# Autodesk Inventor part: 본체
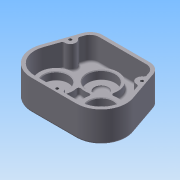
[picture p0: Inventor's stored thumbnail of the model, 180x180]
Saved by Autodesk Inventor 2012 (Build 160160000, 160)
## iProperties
Created: 2014-12
Part Number: 본체
Material: 알루미늄-6061
Document SubType Name: Modeling
Designer: Owner
Density: 2.71 g/cm^3
Mass: 613.436 g
Surface Area: 665.18 cm^2
Volume: 226.36 cm^3
Author: Owner
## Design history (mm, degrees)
sketch "스케치1"
  geometry: L1 (0, 0)-(-42.388, -42.388); L2 (0, 0)-(24.229, -24.229); L3 (-47, 36)-(47, 36); L4 (-47, 36)-(-66.565, -20.803); L5 (47, 36)-(66.565, -20.803); L6 (-32.527, -68.527)-(32.527, -68.527); A1 r 46 centre (0, 0) between (32.527, -32.527) and (-32.527, -32.527); A2 r 36 centre (-32.527, -32.527) between (-66.565, -20.803) and (-32.527, -68.527); A3 r 36 centre (32.527, -32.527) between (32.527, -68.527) and (66.565, -20.803); 3 further points
  constraints: 12 end point, 6 point on circle, 3 centre point, 3 tangent, 2 coincident, 2 midpoint, 2 point on line, 2 vertical alignment, 1 horizontal, 1 parallel
  dimensions: "d0" = 92 diameter of A1; "d1" = 90 deg angle of L2 L1; "d2" = 94 distance of L3.start L3.end; "d3" = 36 distance from line of L1.start L3; "d6" = 36 radius of A2; "d7" = 36 radius of A3
extrude "돌출1" new body sketch "스케치1" distance "d8" = 44; taper "d9" = 0 deg
sketch "스케치2"
  geometry: C1 r 20 at (-32.527, -32.527); C2 r 20 at (32.527, -32.527); A1 r 36 centre (-32.527, -32.527) between (-66.565, -20.803) and (-32.527, -68.527) reference; A2 r 36 centre (32.527, -32.527) between (32.527, -68.527) and (66.565, -20.803) reference; 1 further point
  constraints: 2 centre point, 2 coincident
  dimensions: "d10" = 40 diameter of C1; "d11" = 40 diameter of C2
extrude "돌출2" join sketch "스케치2" distance "d12" = 7; taper "d13" = 0 deg
chamfer "모따기1" distance "d14" = 7; stored, may be unused: second distance "d15" = 2, angle "d16" = 10 deg
sketch "스케치3"
  geometry: L1 (0, -44)-(94, -44) reference; L2 (94, 0)-(94, -44) reference; L3 (0, 0)-(94, 0) reference; L4 (0, 0)-(0, -44) reference; L5 (0, -44)-(0, 0) reference; L6 (0, 0)-(94, 0) reference; L7 (94, 0)-(94, -44) reference; L8 (94, -44)-(0, -44) reference; L9 (60.761, 7)-(59.527, 0) reference; L10 (79.527, 0)-(14.473, 0) reference; 1 further point
  node "절단 모서리 투영1"
chamfer "모따기2" distance "d17" = 7; stored, may be unused: second distance "d18" = 2, angle "d19" = 10 deg
fillet "모깎기1" dims "d20" = 18
hole "구멍1" diameter "d23" = 15.5; stored, may be unused: countersink angle "d27" = 90 deg, drill point angle "d29" = 118 deg; dims "d21" = 10, "d22" = 10, "d24" = 6, "d25" = 4, "d26" = 2, "d28" = 8
hole "구멍2" diameter "d32" = 15.5; stored, may be unused: countersink angle "d36" = 90 deg, drill point angle "d38" = 118 deg; dims "d30" = 10, "d31" = 10, "d33" = 6, "d34" = 4, "d35" = 2, "d37" = 8
hole "구멍3" diameter "d41" = 30; stored, may be unused: countersink angle "d45" = 90 deg, drill point angle "d47" = 0 deg; dims "d39" = 10, "d40" = 10, "d42" = 6, "d43" = 4, "d44" = 2, "d46" = 7
hole "구멍4" diameter "d50" = 30; stored, may be unused: countersink angle "d54" = 90 deg, drill point angle "d56" = 0 deg; dims "d48" = 10, "d49" = 10, "d51" = 6, "d52" = 4, "d53" = 2, "d55" = 7
chamfer "모따기3" distance "d57" = 1; stored, may be unused: second distance "d58" = 2, angle "d59" = 45 deg
fillet "모깎기2" dims "d60" = 3
fillet "모깎기3" dims "d61" = 3
node "작업 평면1"
sketch "스케치4"
  geometry: L1 (34.162, 36)-(-34.162, 36) reference; 2 further points
  constraints: 1 vertical alignment, 1 other
  dimensions: "d63" = 30 distance from line of point (0, 6) L1
feature "엠보싱1" sketch "스케치4" dims "d0" = 92, "d1" = 90 deg, "d2" = 94, "d3" = 36, "d6" = 36, "d7" = 36, "d64" = 1, "d65" = 0
sketch "스케치5"
  geometry: C1 r 20 at (0, 0); 1 further point
  constraints: 1 centre point, 1 coincident
  dimensions: "d66" = 40 diameter of C1
extrude "돌출3" cut sketch "스케치5" distance "d67" = 35; taper "d68" = 0 deg
hole "구멍5" diameter "d71" = 20; stored, may be unused: countersink angle "d75" = 90 deg, drill point angle "d77" = 0 deg; dims "d69" = 10, "d70" = 10, "d72" = 6, "d73" = 4, "d74" = 2, "d76" = 3
fillet "모깎기4" dims "d78" = 0.3
fillet "모깎기5" dims "d79" = 3
sketch "스케치8"
  geometry: L1 (-66.565, -20.803)-(-51.181, 23.862) reference; L2 (51.181, 23.862)-(66.565, -20.803) reference; L3 (-34.162, 31)-(34.162, 31); L4 (-32.527, -63.527)-(32.527, -63.527); L5 (-46.453, 22.233)-(-61.837, -22.432); L6 (46.453, 22.233)-(61.837, -22.432); C1 r 7.75 at (-32.527, -32.527) reference; C2 r 7.75 at (32.527, -32.527) reference; A1 r 36 centre (-32.527, -32.527) between (-66.565, -20.803) and (-32.527, -68.527) reference; A2 r 36 centre (32.527, -32.527) between (32.527, -68.527) and (66.565, -20.803) reference; A3 r 18 centre (34.162, 18) between (51.181, 23.862) and (34.162, 36) reference; A4 r 13 centre (-34.162, 18) between (-34.162, 31) and (-46.453, 22.233); A5 r 13 centre (34.162, 18) between (46.453, 22.233) and (34.162, 31); A6 r 31 centre (-32.527, -32.527) between (-61.837, -22.432) and (-32.527, -63.527); A7 r 31 centre (32.527, -32.527) between (32.527, -63.527) and (61.837, -22.432); 2 further points
  constraints: 8 end point, 8 point on circle, 5 tangent, 4 centre point, 3 coincident, 3 parallel, 1 midpoint, 1 vertical alignment
  dimensions: "d83" = 5 radial gap between concentric circles of A6 A1
extrude "돌출4" cut sketch "스케치8" distance "d84" = 23; taper "d85" = 0 deg
hole "구멍6" diameter "d88" = 35; stored, may be unused: countersink angle "d92" = 90 deg, drill point angle "d94" = 0 deg; dims "d86" = 10, "d87" = 10, "d89" = 6, "d90" = 4, "d91" = 2, "d93" = 11
hole "구멍7" diameter "d97" = 35; stored, may be unused: countersink angle "d101" = 90 deg, drill point angle "d103" = 0 deg; dims "d95" = 10, "d96" = 10, "d98" = 6, "d99" = 4, "d100" = 2, "d102" = 11
sketch "스케치9"
  geometry: L1 (-61.837, -22.432)-(-46.453, 22.233) reference; L2 (-34.162, 31)-(34.162, 31) reference; L3 (46.453, 22.233)-(61.837, -22.432) reference; L4 (32.527, -63.527)-(-32.527, -63.527) reference; C1 r 20 at (0, 0) reference; C2 r 24 at (32.527, -32.527); C3 r 24 at (-32.527, -32.527); C4 r 24 at (0, 0); A1 r 13 centre (-34.162, 18) between (-34.162, 31) and (-46.453, 22.233) reference; A2 r 31 centre (-32.527, -32.527) between (-61.837, -22.432) and (-32.527, -63.527) reference; A3 r 31 centre (32.527, -32.527) between (32.527, -63.527) and (61.837, -22.432) reference; A4 r 13 centre (-34.162, 18) between (-34.162, 31) and (-46.453, 22.233) reference; A5 r 13 centre (34.162, 18) between (46.453, 22.233) and (34.162, 31) reference; A6 r 31 centre (32.527, -32.527) between (32.527, -63.527) and (61.837, -22.432) reference
  constraints: 3 centre point, 3 coincident
  dimensions: "d104" = 48 diameter of C2; "d105" = 48 diameter of C3; "d106" = 48 diameter of C4
extrude "돌출5" cut sketch "스케치9" distance "d107" = 11; taper "d108" = 0 deg
fillet "모깎기6" dims "d109" = 3
chamfer "모따기4" distance "d110" = 1; stored, may be unused: second distance "d111" = 2, angle "d112" = 45 deg
fillet "모깎기7" dims "d113" = 3
fillet "모깎기8" dims "d114" = 3
fillet "모깎기9" dims "d115" = 3
sketch "스케치10"
  geometry: L1 (46.453, 22.233)-(61.837, -22.432) reference; L2 (32.527, -63.527)-(-32.527, -63.527) reference; L3 (-61.837, -22.432)-(-46.453, 22.233) reference; L4 (51.181, 23.862)-(66.565, -20.803) reference; L5 (-34.162, 36)-(34.162, 36) reference; L6 (-49.095, 14.564)-(-54.305, -0.564); L7 (49.095, 14.564)-(54.305, -0.564); L8 (-8, -63.527)-(8, -63.527); A1 r 8 centre (51.7, 7) between (49.095, 14.564) and (54.305, -0.564); A2 r 8 centre (-51.7, 7) between (-54.305, -0.564) and (-49.095, 14.564); A3 r 8 centre (0, -63.527) between (8, -63.527) and (-8, -63.527); 1 further point
  constraints: 8 point on line, 6 end point, 6 point on circle, 3 centre point, 2 parallel, 1 collinear, 1 midpoint
  dimensions: "d116" = 29 distance from line of A1.centre L5; "d117" = 29 distance from line of A2.centre L5; "d121" = 8 radius of A3; "d122" = 8 radius of A1; "d123" = 8 radius of A2
extrude "돌출6" join sketch "스케치10" stored distance "d124" = 11; taper "d125" = 0 deg
fillet "모깎기10" dims "d126" = 3
sketch "스케치11"
  geometry: A1 r 8 centre (51.7, 7) between (47.131, 13.567) and (52.144, -0.988) reference; A2 r 8 centre (0, -63.527) between (7.697, -61.345) and (-7.697, -61.345) reference; A3 r 8 centre (-51.7, 7) between (-52.144, -0.988) and (-47.131, 13.567) reference; 4 further points
  constraints: 3 coincident
hole "구멍8" sketch "스케치11" at (-51.7, 7), (0, -63.527), (51.7, 7) diameter "d127" = 4.134; stored, may be unused: countersink angle "d131" = 90 deg, drill point angle "d133" = 118 deg; dims "d128" = 20, "d129" = 4, "d130" = 2, "d132" = 23
fillet "모깎기11" dims "d137" = 0.3
chamfer "모따기6" distance "d138" = 1; stored, may be unused: second distance "d139" = 2, angle "d140" = 45 deg
fillet "모깎기12" dims "d141" = 0.1
node "솔리드1"
other parameters: "d4" = 72, "d5" = 72, "d62" = 26.25, "d81" = 5, "d82" = 5, "d118" = 16, "d119" = 16, "d120" = 16
